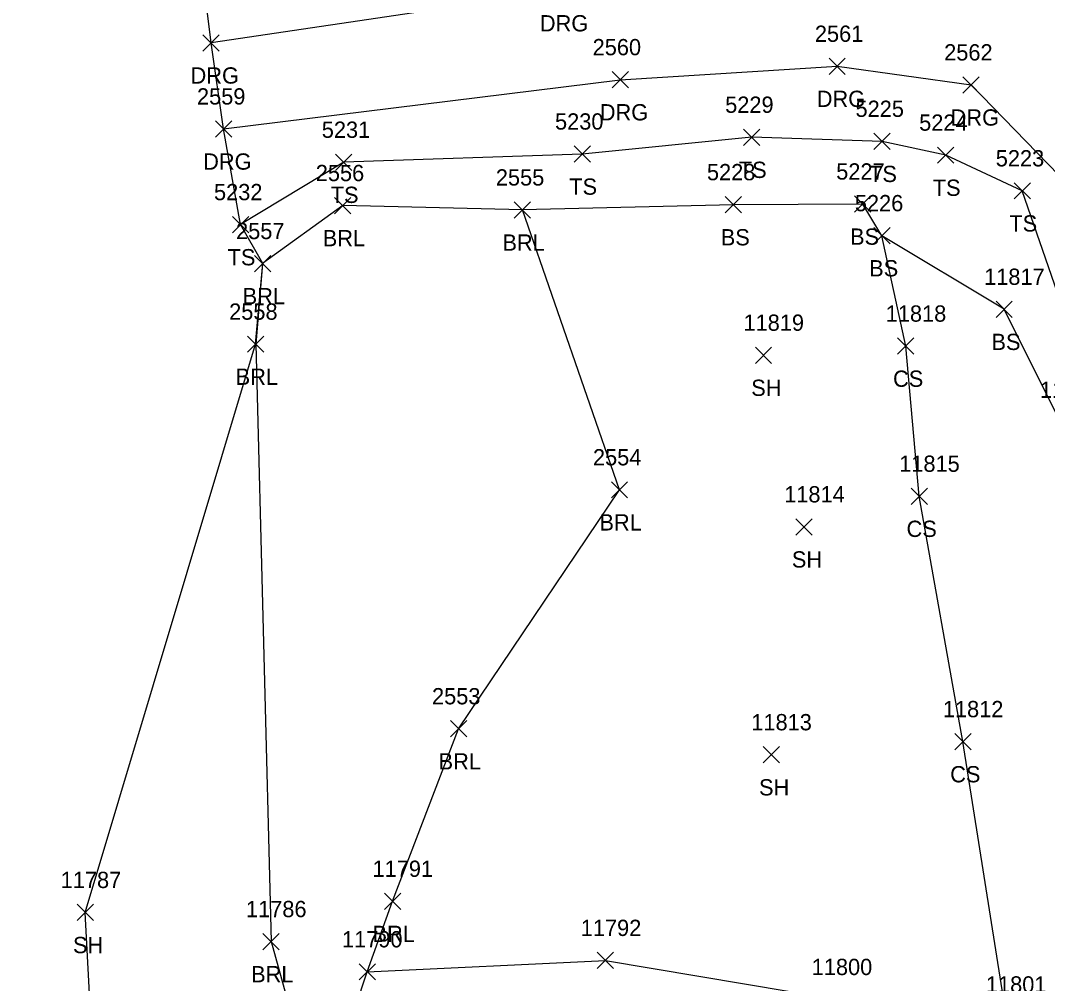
# Model space of a CAD drawing. Extents: x 1439173 to 1457902, y 641926 to 659889.
# Drawn here: x 1447777.6 to 1447903.7, y 648625.8 to 648744.1 of the extents above; entities that cross this region are included whole.
import ezdxf

# ---------------------------------------------------------------- set-up
doc = ezdxf.new("R2010")
doc.units = 0
for name, color, linetype in [('L_A', 7, 'Continuous'), ('L_I', 7, 'Continuous'), ('L_TIC', 7, 'Continuous'), ('LABL', 7, 'Continuous'), ('LELB', 7, 'Continuous'), ('LSOGP', 7, 'Continuous'), ('R_A', 7, 'Continuous'), ('R_I', 7, 'Continuous'), ('R_TIC', 7, 'Continuous'), ('RDG', 7, 'Continuous')]:
    doc.layers.add(name, color=color, linetype=linetype)

msp = doc.modelspace()

# ---------------------------------------------------------------- linework, layer by layer
at = {"layer": 'L_TIC'}
for points in [[(1447866.39, 648728.73), (1447868.39, 648730.73)], [(1447868.39, 648728.73), (1447866.39, 648730.73)], [(1447882.39, 648728.23), (1447884.39, 648730.23)], [(1447884.39, 648728.23), (1447882.39, 648730.23)], [(1447845.57, 648726.67), (1447847.57, 648728.67)], [(1447847.57, 648726.67), (1447845.57, 648728.67)], [(1447890.21, 648726.53), (1447892.21, 648728.53)], [(1447892.21, 648726.53), (1447890.21, 648728.53)], [(1447816.26, 648725.66), (1447818.26, 648727.66)], [(1447818.26, 648725.66), (1447816.26, 648727.66)], [(1447899.62, 648722.15), (1447901.62, 648724.15)], [(1447901.62, 648722.15), (1447899.62, 648724.15)], [(1447816.14, 648720.34), (1447818.14, 648722.34)], [(1447818.14, 648720.34), (1447816.14, 648722.34)], [(1447864.14, 648720.45), (1447866.14, 648722.45)], [(1447866.14, 648720.45), (1447864.14, 648722.45)], [(1447880.02, 648720.53), (1447882.02, 648722.53)], [(1447882.02, 648720.53), (1447880.02, 648722.53)], [(1447838.21, 648719.8), (1447840.21, 648721.8)], [(1447840.21, 648719.8), (1447838.21, 648721.8)], [(1447803.59, 648718), (1447805.59, 648720)], [(1447805.59, 648718), (1447803.59, 648720)], [(1447882.37, 648716.64), (1447884.37, 648718.64)], [(1447884.37, 648716.64), (1447882.37, 648718.64)], [(1447806.3, 648713.22), (1447808.3, 648715.22)], [(1447808.3, 648713.22), (1447806.3, 648715.22)], [(1447897.39, 648707.6), (1447899.39, 648709.6)], [(1447899.39, 648707.6), (1447897.39, 648709.6)], [(1447805.45, 648703.32), (1447807.45, 648705.32)], [(1447807.45, 648703.32), (1447805.45, 648705.32)], [(1447885.3, 648703.08), (1447887.3, 648705.08)], [(1447887.3, 648703.08), (1447885.3, 648705.08)], [(1447867.83, 648701.96), (1447869.83, 648703.96)], [(1447869.83, 648701.96), (1447867.83, 648703.96)], [(1447850.14, 648685.43), (1447852.14, 648687.43)], [(1447852.14, 648685.43), (1447850.14, 648687.43)], [(1447886.96, 648684.64), (1447888.96, 648686.64)], [(1447888.96, 648684.64), (1447886.96, 648686.64)], [(1447872.82, 648680.88), (1447874.82, 648682.88)], [(1447874.82, 648680.88), (1447872.82, 648682.88)], [(1447830.37, 648656.08), (1447832.37, 648658.08)], [(1447832.37, 648656.08), (1447830.37, 648658.08)], [(1447892.32, 648654.5), (1447894.32, 648656.5)], [(1447894.32, 648654.5), (1447892.32, 648656.5)], [(1447868.79, 648652.89), (1447870.79, 648654.89)], [(1447870.79, 648652.89), (1447868.79, 648654.89)], [(1447822.26, 648634.89), (1447824.26, 648636.89)], [(1447824.26, 648634.89), (1447822.26, 648636.89)], [(1447784.52, 648633.52), (1447786.52, 648635.52)], [(1447786.52, 648633.52), (1447784.52, 648635.52)], [(1447807.34, 648629.94), (1447809.34, 648631.94)], [(1447809.34, 648629.94), (1447807.34, 648631.94)], [(1447848.41, 648627.63), (1447850.41, 648629.63)], [(1447850.41, 648627.63), (1447848.41, 648629.63)], [(1447819.16, 648626.23), (1447821.16, 648628.23)], [(1447821.16, 648626.23), (1447819.16, 648628.23)], [(1447819.16, 648626.23), (1447821.16, 648628.23)], [(1447821.16, 648626.23), (1447819.16, 648628.23)]]:
    msp.add_lwpolyline(points, dxfattribs=at)
at = {"layer": 'LABL'}
for points in [[(1447831.37, 648657.08), (1447851.14, 648686.43), (1447839.21, 648720.8), (1447817.14, 648721.34), (1447807.3, 648714.22), (1447806.45, 648704.32)], [(1447806.45, 648704.32), (1447808.34, 648630.94)], [(1447823.26, 648635.89), (1447831.37, 648657.08)], [(1447808.34, 648630.94), (1447814.29, 648609.5), (1447820.16, 648627.23), (1447823.26, 648635.89)]]:
    msp.add_lwpolyline(points, dxfattribs=at)
at = {"layer": 'LELB'}
for points in [[(1447900.62, 648723.15), (1447891.21, 648727.53), (1447883.39, 648729.23), (1447867.39, 648729.73), (1447846.57, 648727.67), (1447817.26, 648726.66), (1447804.59, 648719)], [(1447909.66, 648697.05), (1447900.62, 648723.15)], [(1447865.14, 648721.45), (1447839.21, 648720.8)], [(1447883.37, 648717.64), (1447881.02, 648721.53), (1447865.14, 648721.45)], [(1447898.39, 648708.6), (1447883.37, 648717.64)], [(1447886.3, 648704.08), (1447883.37, 648717.64)], [(1447857.92, 648532.04), (1447874.33, 648528.1), (1447893.57, 648529.78), (1447914.68, 648536.88), (1447921.41, 648543.42), (1447921.85, 648560.74), (1447920.34, 648585.99), (1447914.48, 648614.57), (1447909.22, 648666.97), (1447905.3, 648694.72), (1447898.39, 648708.6)], [(1447820.16, 648627.23), (1447849.41, 648628.63), (1447877.94, 648623.83), (1447898.69, 648621.68), (1447893.32, 648655.5), (1447887.96, 648685.64), (1447886.3, 648704.08)]]:
    msp.add_lwpolyline(points, dxfattribs=at)
at = {"layer": 'LSOGP'}
msp.add_lwpolyline([(1447821.27, 648293.77), (1447805.14, 648342.09), (1447804.36, 648349.32), (1447796.43, 648362.58), (1447792.31, 648372.38), (1447795.05, 648396.42), (1447796.19, 648411.29), (1447785.88, 648452.99), (1447780.78, 648490.7), (1447777.56, 648514.38), (1447782.67, 648520.33), (1447781.51, 648533.74), (1447778.72, 648568.12), (1447787.13, 648603.86), (1447785.52, 648634.52), (1447806.44, 648704.32), (1447807.31, 648714.22), (1447804.59, 648719), (1447802.51, 648730.75), (1447800.97, 648741.32), (1447799.79, 648750.94)], dxfattribs=at)
at = {"layer": 'R_TIC'}
for points in [[(1447799.97, 648740.32), (1447801.97, 648742.32)], [(1447801.97, 648740.32), (1447799.97, 648742.32)], [(1447876.88, 648737.45), (1447878.88, 648739.45)], [(1447878.88, 648737.45), (1447876.88, 648739.45)], [(1447850.24, 648735.8), (1447852.24, 648737.8)], [(1447852.24, 648735.8), (1447850.24, 648737.8)], [(1447893.33, 648735.16), (1447895.33, 648737.16)], [(1447895.33, 648735.16), (1447893.33, 648737.16)], [(1447801.51, 648729.75), (1447803.51, 648731.75)], [(1447803.51, 648729.75), (1447801.51, 648731.75)]]:
    msp.add_lwpolyline(points, dxfattribs=at)
at = {"layer": 'RDG'}
for points in [[(1447846.13, 648867.73), (1447848.96, 648867.78), (1447850.86, 648861.63), (1447855.56, 648824.95), (1447851.08, 648818.41), (1447842.54, 648818.06), (1447840.37, 648829.25), (1447823.51, 648827.34), (1447826.51, 648808.46), (1447827.03, 648788.95), (1447830.16, 648773.87), (1447845.01, 648772.87), (1447846.68, 648786.35), (1447851.07, 648796.12), (1447860.09, 648784.68), (1447863.97, 648766.34), (1447861.73, 648752.31), (1447843.87, 648747.73), (1447800.97, 648741.32)], [(1447802.51, 648730.75), (1447851.24, 648736.8), (1447877.88, 648738.45), (1447894.33, 648736.16), (1447909.17, 648720.89)]]:
    msp.add_lwpolyline(points, dxfattribs=at)

# ---------------------------------------------------------------- texts
at = {"layer": 'L_A'}
for s, p in [('TS', (1447865.8, 648724.73)), ('TS', (1447881.8, 648724.23)), ('TS', (1447844.97, 648722.67)), ('TS', (1447815.67, 648721.66)), ('TS', (1447889.62, 648722.53)), ('TS', (1447899.03, 648718.15)), ('BRL', (1447814.69, 648716.34)), ('BS', (1447863.58, 648716.45)), ('BS', (1447879.46, 648716.53)), ('BRL', (1447836.76, 648715.8)), ('TS', (1447803, 648714)), ('BS', (1447881.81, 648712.64)), ('BRL', (1447804.85, 648709.22)), ('BS', (1447896.83, 648703.6)), ('BRL', (1447803.99, 648699.32)), ('CS', (1447884.74, 648699.08)), ('SH', (1447867.32, 648697.96)), ('BRL', (1447848.68, 648681.43)), ('CS', (1447886.4, 648680.64)), ('SH', (1447872.31, 648676.88)), ('BRL', (1447828.92, 648652.08)), ('CS', (1447891.76, 648650.5)), ('SH', (1447868.28, 648648.89)), ('BRL', (1447820.8, 648630.89)), ('SH', (1447784.01, 648629.52)), ('BRL', (1447805.89, 648625.94))]:
    msp.add_text(s, height=2, dxfattribs=at).set_placement(p)
at = {"layer": 'L_I'}
for s, p in [('5229', (1447864.12, 648732.73)), ('5225', (1447880.13, 648732.23)), ('5230', (1447843.22, 648730.67)), ('5224', (1447887.95, 648730.53)), ('5231', (1447814.57, 648729.66)), ('5223', (1447897.36, 648726.15)), ('2556', (1447813.83, 648724.34)), ('5228', (1447861.88, 648724.45)), ('5227', (1447877.76, 648724.53)), ('2555', (1447835.95, 648723.8)), ('5232', (1447801.33, 648722)), ('5226', (1447880.05, 648720.64)), ('2557', (1447804.04, 648717.22)), ('11817', (1447895.93, 648711.6)), ('2558', (1447803.19, 648707.32)), ('11818', (1447883.84, 648707.08)), ('11819', (1447866.37, 648705.96)), ('11816', (1447902.79, 648697.72)), ('2554', (1447847.88, 648689.43)), ('11815', (1447885.5, 648688.64)), ('11814', (1447871.37, 648684.88)), ('2553', (1447828.11, 648660.08)), ('11812', (1447890.86, 648658.5)), ('11813', (1447867.33, 648656.89)), ('11791', (1447820.8, 648638.89)), ('11787', (1447782.5, 648637.52)), ('11786', (1447805.26, 648633.94)), ('11792', (1447846.38, 648631.63)), ('11790', (1447817.05, 648630.23)), ('11790', (1447817.05, 648630.23)), ('11800', (1447874.75, 648626.83)), ('11801', (1447896.15, 648624.68))]:
    msp.add_text(s, height=2, dxfattribs=at).set_placement(p)
at = {"layer": 'R_A'}
for p in [(1447841.36, 648742.73), (1447798.45, 648736.32), (1447875.37, 648733.45), (1447848.72, 648731.8), (1447891.82, 648731.16), (1447800, 648725.75)]:
    msp.add_text('DRG', height=2, dxfattribs=at).set_placement(p)
at = {"layer": 'R_I'}
for s, p in [('2561', (1447875.14, 648741.45)), ('2560', (1447847.84, 648739.8)), ('2562', (1447891.02, 648739.16)), ('2559', (1447799.24, 648733.75))]:
    msp.add_text(s, height=2, dxfattribs=at).set_placement(p)

doc.saveas('drawing.dxf')
